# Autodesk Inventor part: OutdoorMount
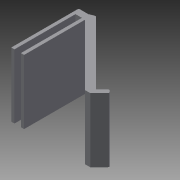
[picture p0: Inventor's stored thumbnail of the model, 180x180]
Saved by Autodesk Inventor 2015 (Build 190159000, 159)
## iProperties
Created: 2017-04
Part Number: OutdoorMount
Material: Generisch
Document SubType Name: Modeling
Designer: Andreas
Density: 1 g/cm^3
Appearance: Vorgabe
Author: Andreas
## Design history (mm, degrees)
sketch "Skizze1"
  geometry: L1 (0, 0)-(0, 105); L2 (0, 105)-(20, 105); L3 (0, 0)-(5, 0); L4 (5, 0)-(5, 95); L5 (5, 95)-(15, 95); L6 (15, 95)-(15, 0); L7 (15, 0)-(20, 0); L8 (20, 0)-(20, 95); L9 (25, 105)-(143.136, 105); L10 (20, 95)-(115, 0); L11 (20, 95)-(154.35, 95); L12 (118.995, 6.005)-(20, 105); L13 (118.995, 6.005)-(258.995, 6.005); L14 (118.995, 6.005)-(133.137, 20.147); L15 (118.995, 6.005)-(138.995, 6.005); L16 (133.137, 20.147)-(138.087, 15.197); L17 (138.087, 15.197)-(122.889, 0); L18 (122.889, 0)-(115, 0)
  constraints: 36 end point, 8 horizontal, 5 perpendicular, 3 equal length, 2 vertical, 1 point on line
  dimensions: "d0" = 105 distance of L1.start L1.end; "d2" = 5 distance of L1.start L3.end; "d3" = 95 distance of L3.end L4.end; "d4" = 10 distance of L4.end L5.end; "d5" = 5 distance of L6.end L7.end; "d6" = 95 distance of L7.end L8.end; "d27" = 45 deg angle of L10 L11; "d29" = 135 deg angle of L13 L12; "d30" = 20 distance of L12.start L14.end; "d31" = 45 deg angle of L15 L14 (derived); "d34" = 140 distance of L12.start L2.end; "d35" = 20 distance of L1.end L2.end; "d36" = 7 distance of L14.end L16.end; "d37" = 7.88939 distance of L17.end L10.end; "d38" = 135 deg angle of L18 L17
extrude "Extrusion1" new body sketch "Skizze1" distance "d39" = 100; taper "d40" = 0 deg
sketch "Skizze2"
  geometry: C1 r 15 at (-70.711, 50); 2 further points
  constraints: 1 centre point, 1 coincident
  dimensions: "d41" = 30 diameter of C1
extrude "Extrusion2" cut sketch "Skizze2" distance "d42" = 8; taper "d43" = 0 deg
sketch "Skizze3"
  geometry: L1 (20, 105)-(25, 105); L2 (23.536, 108.536)-(122.53, 9.541); L3 (133.137, 20.147)-(118.995, 6.005) reference; L4 (122.53, 9.541)-(118.995, 6.005); L5 (118.995, 6.005)-(20, 105); L6 (20, 105)-(0, 105) reference; L7 (23.536, 108.536)-(15, 105); 1 further point
  constraints: 10 end point, 2 point on line, 1 collinear, 1 horizontal
  dimensions: "d44" = 5 distance of L1.start L2.start; "d47" = 112.5 deg angle of L2 L7; "d48" = 157.5 deg angle of L7 L6; "d49" = 8.53553 horizontal distance of L2.start L7.end
extrude "Extrusion3" join sketch "Skizze3" distance "d50" = 2.5; taper "d51" = 0 deg
sketch "Skizze4"
  geometry: L1 (-20, 105)-(-118.995, 6.005); L2 (-118.995, 6.005)-(-133.137, 20.147) reference; L3 (-118.995, 6.005)-(-122.53, 9.541); L4 (-122.53, 9.541)-(-23.536, 108.536); L5 (-23.536, 108.536)-(-122.53, 9.541) reference; L6 (-23.536, 108.536)-(-15, 105); L7 (-15, 105)-(-23.536, 108.536) reference; L8 (-15, 105)-(-20, 105); L9 (0, 105)-(-20, 105) reference; 1 further point
  constraints: 10 end point, 3 collinear, 1 perpendicular, 1 point on line
  dimensions: "d52" = 5 distance of L1.end L3.end
extrude "Extrusion4" join sketch "Skizze4" distance "d53" = 2.5; taper "d54" = 0 deg
fillet "Rundung1" dims "d55" = 3
fillet "Rundung2" dims "d56" = 3
fillet "Rundung3" dims "d57" = 2
fillet "Rundung4" dims "d58" = 2
fillet "Rundung5" dims "d59" = 3
fillet "Rundung6" dims "d60" = 3
fillet "Rundung7" dims "d61" = 2
fillet "Rundung8" dims "d62" = 2
node "Volumenkörper1"
